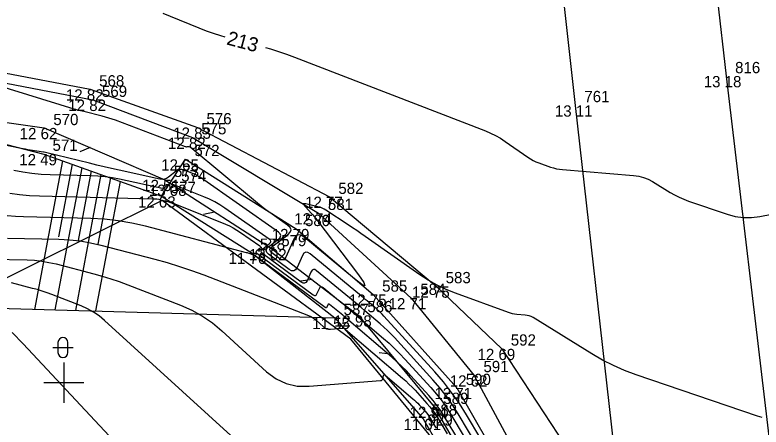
# Model space of a CAD drawing. Extents: x -711234 to -710007, y -1026313 to -1025448.
# Drawn here: x -710926.22 to -710907.65, y -1025876.1 to -1025865.86 of the extents above; entities that cross this region are included whole.
import ezdxf

# ---------------------------------------------------------------- set-up
doc = ezdxf.new("R2010")
doc.units = 0
for name, color, linetype in [('Ex_Contour Labels', 7, 'Continuous'), ('Ex_Major Contours', 7, 'Continuous'), ('Ex_Minor Contours', 7, 'Continuous'), ('Z_betonova_konstrukce', 7, 'Continuous'), ('Z_body', 7, 'Continuous'), ('Z_body_cisla', 7, 'Continuous'), ('Z_body_vysky_redukovane', 7, 'Continuous'), ('Z_hektometricka_sit', 7, 'Continuous'), ('Z_hrany_paty', 7, 'Continuous'), ('Z_katastr_hranice', 7, 'Continuous'), ('Z_katastr_znacky_kultur', 7, 'Continuous'), ('Z_komunikace', 7, 'Continuous'), ('Z_svodidla', 7, 'Continuous'), ('Z_svodidla_znacky', 7, 'Continuous'), ('Z_technicke_srafy', 7, 'Continuous'), ('Z_vdz12_prerusovana', 7, 'Continuous'), ('Z_vdz25_plna', 7, 'Continuous'), ('Z_vdz25_prerusovana', 7, 'Continuous')]:
    doc.layers.add(name, color=color, linetype=linetype)

# ---------------------------------------------------------------- blocks, each defined once
blk = doc.blocks.new('POINT_DISPLAY')
blk.add_line((0, 0), (0, 0))
blk = doc.blocks.new('Z529')
blk.add_line((0, 0), (0.2, 0.2))

msp = doc.modelspace()

# ---------------------------------------------------------------- linework, layer by layer
at = {"layer": 'Ex_Major Contours'}
for points in [[(-710922.532, -1025865.817), (-710922.354, -1025865.89), (-710921.642, -1025866.183), (-710921.462, -1025866.253), (-710921.281, -1025866.317), (-710921.098, -1025866.375), (-710920.995, -1025866.404)], [(-710919.98, -1025866.673), (-710919.86, -1025866.707), (-710919.659, -1025866.769), (-710919.459, -1025866.836), (-710919.262, -1025866.909), (-710914.512, -1025868.743), (-710914.383, -1025868.798), (-710914.258, -1025868.859), (-710914.137, -1025868.928), (-710914.019, -1025869.005), (-710913.453, -1025869.397), (-710913.389, -1025869.439), (-710913.323, -1025869.476), (-710913.254, -1025869.509), (-710913.183, -1025869.537), (-710912.894, -1025869.642), (-710912.821, -1025869.666), (-710912.747, -1025869.685), (-710912.672, -1025869.698), (-710912.596, -1025869.707), (-710910.824, -1025869.85), (-710910.699, -1025869.867), (-710910.579, -1025869.899), (-710910.464, -1025869.945), (-710910.353, -1025870.004), (-710909.918, -1025870.272), (-710909.808, -1025870.335), (-710909.695, -1025870.392), (-710909.579, -1025870.443), (-710909.46, -1025870.488), (-710908.499, -1025870.815), (-710908.297, -1025870.87), (-710908.094, -1025870.898), (-710907.889, -1025870.898), (-710907.682, -1025870.871), (-710905.856, -1025870.512)], [(-710926.346, -1025870.293), (-710926.098, -1025870.326), (-710925.85, -1025870.349), (-710925.6, -1025870.361), (-710922.778, -1025870.429), (-710922.731, -1025870.431), (-710922.685, -1025870.436), (-710922.639, -1025870.444), (-710922.594, -1025870.455), (-710922.413, -1025870.502), (-710922.368, -1025870.514), (-710922.323, -1025870.528), (-710922.279, -1025870.544), (-710922.235, -1025870.56), (-710920.978, -1025871.065), (-710920.88, -1025871.107), (-710920.785, -1025871.155), (-710920.693, -1025871.208), (-710920.604, -1025871.266), (-710920.12, -1025871.604), (-710920.105, -1025871.618), (-710920.099, -1025871.633), (-710920.104, -1025871.648), (-710920.119, -1025871.663), (-710920.199, -1025871.723), (-710920.214, -1025871.738), (-710920.219, -1025871.753), (-710920.214, -1025871.768), (-710920.199, -1025871.783), (-710918.796, -1025872.821), (-710918.767, -1025872.837), (-710918.742, -1025872.838), (-710918.721, -1025872.825), (-710918.703, -1025872.797), (-710918.64, -1025872.658), (-710918.622, -1025872.63), (-710918.602, -1025872.618), (-710918.577, -1025872.62), (-710918.549, -1025872.637), (-710918.077, -1025873.026), (-710917.989, -1025873.1), (-710917.901, -1025873.173), (-710917.813, -1025873.247), (-710917.725, -1025873.322), (-710917.049, -1025873.9), (-710916.909, -1025874.023), (-710916.774, -1025874.15), (-710916.642, -1025874.282), (-710916.514, -1025874.418), (-710915.869, -1025875.124), (-710915.725, -1025875.291), (-710915.589, -1025875.465), (-710915.462, -1025875.645), (-710915.344, -1025875.833), (-710914.755, -1025876.824)], [(-710920.757, -1025876.401), (-710923.985, -1025873.453), (-710924.117, -1025873.343), (-710924.257, -1025873.247), (-710924.406, -1025873.164), (-710924.564, -1025873.094), (-710925.301, -1025872.81), (-710925.417, -1025872.767), (-710925.536, -1025872.727), (-710925.655, -1025872.69), (-710925.775, -1025872.657), (-710926.299, -1025872.52)]]:
    msp.add_lwpolyline(points, dxfattribs=at)
msp.add_lwpolyline([(-710919.793, -1025871.7), (-710919.79, -1025871.7), (-710919.787, -1025871.698), (-710919.785, -1025871.695), (-710919.766, -1025871.653), (-710919.764, -1025871.647), (-710919.764, -1025871.643), (-710919.767, -1025871.644), (-710919.773, -1025871.648), (-710919.811, -1025871.676), (-710919.814, -1025871.679), (-710919.815, -1025871.681), (-710919.814, -1025871.684), (-710919.811, -1025871.687), (-710919.796, -1025871.698)], close=True, dxfattribs=at)
at = {"layer": 'Ex_Minor Contours'}
for points in [[(-710907.626, -1025875.866), (-710907.741, -1025875.835), (-710910.765, -1025874.804), (-710911.049, -1025874.698), (-710911.327, -1025874.576), (-710911.597, -1025874.44), (-710911.86, -1025874.288), (-710913.327, -1025873.385), (-710913.373, -1025873.36), (-710913.421, -1025873.342), (-710913.47, -1025873.328), (-710913.522, -1025873.321), (-710913.733, -1025873.304), (-710913.785, -1025873.298), (-710913.837, -1025873.289), (-710913.888, -1025873.276), (-710913.938, -1025873.26), (-710915.257, -1025872.781), (-710915.49, -1025872.688), (-710915.715, -1025872.581), (-710915.932, -1025872.458), (-710916.142, -1025872.321), (-710917.503, -1025871.367), (-710917.608, -1025871.294), (-710917.714, -1025871.221), (-710917.821, -1025871.15), (-710917.927, -1025871.078), (-710918.479, -1025870.713), (-710918.525, -1025870.686), (-710918.574, -1025870.662), (-710918.624, -1025870.643), (-710918.676, -1025870.628), (-710918.98, -1025870.557), (-710918.987, -1025870.555), (-710918.995, -1025870.554), (-710919.002, -1025870.554), (-710919.009, -1025870.554), (-710919.038, -1025870.555), (-710919.044, -1025870.555), (-710919.046, -1025870.558), (-710919.046, -1025870.561), (-710919.043, -1025870.566), (-710918.842, -1025870.79), (-710918.807, -1025870.829), (-710918.774, -1025870.869), (-710918.741, -1025870.91), (-710918.709, -1025870.952), (-710917.668, -1025872.325), (-710917.536, -1025872.513), (-710917.509, -1025872.592), (-710917.587, -1025872.562), (-710917.77, -1025872.422), (-710919.032, -1025871.381), (-710919.106, -1025871.336), (-710919.171, -1025871.33), (-710919.226, -1025871.364), (-710919.273, -1025871.437), (-710919.474, -1025871.881), (-710919.503, -1025871.926), (-710919.537, -1025871.947), (-710919.578, -1025871.946), (-710919.625, -1025871.92), (-710919.824, -1025871.773), (-710919.861, -1025871.736), (-710919.874, -1025871.699), (-710919.862, -1025871.662), (-710919.825, -1025871.625), (-710919.429, -1025871.327), (-710919.367, -1025871.265), (-710919.347, -1025871.204), (-710919.369, -1025871.144), (-710919.433, -1025871.085), (-710919.82, -1025870.815), (-710919.912, -1025870.749), (-710920.003, -1025870.682), (-710920.092, -1025870.612), (-710920.179, -1025870.541), (-710921.853, -1025869.146), (-710921.862, -1025869.14), (-710921.871, -1025869.137), (-710921.881, -1025869.135), (-710921.891, -1025869.136), (-710921.934, -1025869.143), (-710921.945, -1025869.145), (-710921.956, -1025869.144), (-710921.966, -1025869.143), (-710921.976, -1025869.139), (-710923.716, -1025868.48), (-710923.796, -1025868.451), (-710923.877, -1025868.424), (-710923.959, -1025868.4), (-710924.042, -1025868.379), (-710924.498, -1025868.266), (-710924.539, -1025868.256), (-710924.58, -1025868.246), (-710924.662, -1025868.225), (-710924.683, -1025868.22), (-710924.703, -1025868.214), (-710924.724, -1025868.209), (-710924.744, -1025868.203), (-710927.51, -1025867.351)], [(-710913.915, -1025877.594), (-710914.983, -1025875.798), (-710915.16, -1025875.517), (-710915.351, -1025875.245), (-710915.555, -1025874.984), (-710915.773, -1025874.732), (-710917.038, -1025873.346), (-710917.081, -1025873.301), (-710917.125, -1025873.257), (-710917.17, -1025873.214), (-710917.216, -1025873.173), (-710917.405, -1025873.012), (-710917.453, -1025872.971), (-710917.5, -1025872.931), (-710917.548, -1025872.891), (-710917.596, -1025872.852), (-710918.871, -1025871.8), (-710918.93, -1025871.764), (-710918.981, -1025871.759), (-710919.025, -1025871.786), (-710919.062, -1025871.844), (-710919.195, -1025872.138), (-710919.232, -1025872.196), (-710919.277, -1025872.224), (-710919.331, -1025872.222), (-710919.391, -1025872.189), (-710919.905, -1025871.809), (-710919.951, -1025871.763), (-710919.967, -1025871.717), (-710919.952, -1025871.671), (-710919.905, -1025871.624), (-710919.659, -1025871.439), (-710919.613, -1025871.393), (-710919.598, -1025871.347), (-710919.614, -1025871.302), (-710919.662, -1025871.258), (-710921.602, -1025869.906), (-710921.65, -1025869.875), (-710921.698, -1025869.847), (-710921.749, -1025869.821), (-710921.8, -1025869.799), (-710922.01, -1025869.715), (-710922.062, -1025869.701), (-710922.111, -1025869.701), (-710922.159, -1025869.715), (-710922.204, -1025869.742), (-710922.398, -1025869.895), (-710922.446, -1025869.925), (-710922.497, -1025869.944), (-710922.552, -1025869.95), (-710922.609, -1025869.943), (-710923.626, -1025869.721), (-710923.81, -1025869.68), (-710923.994, -1025869.638), (-710924.178, -1025869.594), (-710924.362, -1025869.55), (-710925.454, -1025869.281), (-710925.49, -1025869.272), (-710925.499, -1025869.27), (-710925.508, -1025869.269), (-710925.839, -1025869.22), (-710925.895, -1025869.211), (-710925.951, -1025869.202), (-710926.008, -1025869.191), (-710926.064, -1025869.18), (-710927.956, -1025868.79)], [(-710914.335, -1025877.209), (-710915.164, -1025875.815), (-710915.311, -1025875.581), (-710915.47, -1025875.355), (-710915.64, -1025875.137), (-710915.821, -1025874.928), (-710916.776, -1025873.882), (-710916.861, -1025873.791), (-710916.949, -1025873.703), (-710917.04, -1025873.619), (-710917.133, -1025873.536), (-710917.511, -1025873.213), (-710917.606, -1025873.133), (-710917.701, -1025873.052), (-710917.796, -1025872.973), (-710917.892, -1025872.893), (-710918.71, -1025872.218), (-710918.753, -1025872.192), (-710918.791, -1025872.188), (-710918.824, -1025872.208), (-710918.851, -1025872.251), (-710918.949, -1025872.467), (-710918.976, -1025872.51), (-710919.01, -1025872.531), (-710919.049, -1025872.529), (-710919.094, -1025872.505), (-710920.052, -1025871.796), (-710920.083, -1025871.765), (-710920.093, -1025871.735), (-710920.083, -1025871.704), (-710920.052, -1025871.674), (-710919.889, -1025871.551), (-710919.858, -1025871.52), (-710919.849, -1025871.49), (-710919.859, -1025871.46), (-710919.891, -1025871.431), (-710920.99, -1025870.665), (-710921.116, -1025870.583), (-710921.246, -1025870.508), (-710921.379, -1025870.44), (-710921.517, -1025870.38), (-710922.305, -1025870.064), (-710922.331, -1025870.057), (-710922.355, -1025870.057), (-710922.379, -1025870.064), (-710922.401, -1025870.078), (-710922.489, -1025870.147), (-710922.512, -1025870.162), (-710922.536, -1025870.17), (-710922.561, -1025870.173), (-710922.588, -1025870.17), (-710923.612, -1025869.946), (-710923.792, -1025869.911), (-710923.973, -1025869.885), (-710924.156, -1025869.868), (-710924.339, -1025869.859), (-710925.339, -1025869.835), (-710925.566, -1025869.824), (-710925.792, -1025869.804), (-710926.017, -1025869.773), (-710926.241, -1025869.732)], [(-710915.158, -1025876.467), (-710915.525, -1025875.85), (-710915.613, -1025875.71), (-710915.708, -1025875.575), (-710915.809, -1025875.445), (-710915.918, -1025875.32), (-710916.364, -1025874.831), (-710916.478, -1025874.71), (-710916.595, -1025874.593), (-710916.715, -1025874.48), (-710916.839, -1025874.371), (-710918.022, -1025873.36), (-710918.061, -1025873.327), (-710918.1, -1025873.294), (-710918.139, -1025873.261), (-710918.179, -1025873.228), (-710918.389, -1025873.055), (-710918.401, -1025873.048), (-710918.412, -1025873.047), (-710918.421, -1025873.052), (-710918.429, -1025873.064), (-710918.457, -1025873.126), (-710918.465, -1025873.139), (-710918.474, -1025873.145), (-710918.485, -1025873.144), (-710918.498, -1025873.137), (-710920.205, -1025871.874), (-710920.223, -1025871.861), (-710920.242, -1025871.85), (-710920.262, -1025871.84), (-710920.283, -1025871.831), (-710920.366, -1025871.799), (-710920.388, -1025871.791), (-710920.409, -1025871.784), (-710920.43, -1025871.777), (-710920.452, -1025871.771), (-710922.968, -1025871.115), (-710923.304, -1025871.038), (-710923.644, -1025870.98), (-710923.986, -1025870.942), (-710924.331, -1025870.924), (-710926.001, -1025870.883), (-710926.204, -1025870.874), (-710926.406, -1025870.856)], [(-710926.403, -1025871.406), (-710925.122, -1025871.437), (-710924.858, -1025871.451), (-710924.596, -1025871.48), (-710924.336, -1025871.524), (-710924.078, -1025871.584), (-710922.735, -1025871.934), (-710922.427, -1025872.019), (-710922.122, -1025872.112), (-710921.82, -1025872.215), (-710921.52, -1025872.325), (-710918.91, -1025873.333), (-710918.858, -1025873.356), (-710918.809, -1025873.383), (-710918.763, -1025873.415), (-710918.72, -1025873.451), (-710918.542, -1025873.613), (-710918.503, -1025873.643), (-710918.461, -1025873.663), (-710918.415, -1025873.673), (-710918.366, -1025873.674), (-710918.07, -1025873.65), (-710918.067, -1025873.649), (-710918.064, -1025873.648), (-710918.062, -1025873.646), (-710918.061, -1025873.643), (-710918.058, -1025873.629), (-710918.057, -1025873.626), (-710918.055, -1025873.625), (-710918.053, -1025873.625), (-710918.051, -1025873.627), (-710916.576, -1025874.887), (-710916.494, -1025874.96), (-710916.414, -1025875.035), (-710916.336, -1025875.112), (-710916.261, -1025875.192), (-710915.966, -1025875.516), (-710915.894, -1025875.599), (-710915.827, -1025875.685), (-710915.764, -1025875.774), (-710915.706, -1025875.867), (-710915.463, -1025876.275)], [(-710926.804, -1025871.929), (-710925.914, -1025871.95), (-710925.731, -1025871.96), (-710925.549, -1025871.98), (-710925.368, -1025872.011), (-710925.189, -1025872.052), (-710924.255, -1025872.295), (-710924.041, -1025872.354), (-710923.829, -1025872.419), (-710923.619, -1025872.491), (-710923.41, -1025872.568), (-710922.098, -1025873.075), (-710921.817, -1025873.198), (-710921.552, -1025873.345), (-710921.302, -1025873.517), (-710921.066, -1025873.713), (-710919.954, -1025874.729), (-710919.719, -1025874.906), (-710919.465, -1025875.025), (-710919.191, -1025875.087), (-710918.898, -1025875.092), (-710917.119, -1025874.95), (-710917.1, -1025874.946), (-710917.085, -1025874.937), (-710917.074, -1025874.924), (-710917.067, -1025874.906), (-710917.048, -1025874.825), (-710917.041, -1025874.809), (-710917.032, -1025874.801), (-710917.021, -1025874.802), (-710917.006, -1025874.812), (-710916.313, -1025875.404), (-710916.272, -1025875.439), (-710916.233, -1025875.476), (-710916.195, -1025875.514), (-710916.159, -1025875.553), (-710916.014, -1025875.712), (-710915.979, -1025875.752), (-710915.946, -1025875.795), (-710915.915, -1025875.838), (-710915.887, -1025875.884), (-710915.768, -1025876.084), (-710915.739, -1025876.133)], [(-710926.286, -1025873.758), (-710926.192, -1025873.849), (-710926.1, -1025873.942), (-710926.01, -1025874.036), (-710922.921, -1025877.343)]]:
    msp.add_lwpolyline(points, dxfattribs=at)
at = {"layer": 'Z_betonova_konstrukce'}
for p, q in [((-710922.57, -1025870.37), (-710921.97, -1025869.45)), ((-710921.97, -1025869.45), (-710919.22, -1025871.18)), ((-710922.57, -1025870.37), (-710920.34, -1025871.77)), ((-710919.22, -1025871.18), (-710917.3, -1025872.81)), ((-710920.34, -1025871.77), (-710918.26, -1025873.39)), ((-710917.3, -1025872.81), (-710915.22, -1025875.13)), ((-710918.26, -1025873.39), (-710916.06, -1025875.9)), ((-710915.22, -1025875.13), (-710913.68, -1025877.81)), ((-710916.06, -1025875.9), (-710914.66, -1025878.32))]:
    msp.add_line(p, q, dxfattribs=at)
at = {"layer": 'Z_hektometricka_sit'}
for p, q in [((-710925, -1025874.5), (-710925, -1025875.5)), ((-710925.5, -1025875), (-710924.5, -1025875))]:
    msp.add_line(p, q, dxfattribs=at)
at = {"layer": 'Z_hrany_paty'}
for p, q in [((-710928.21, -1025868.62), (-710925.5, -1025869.32)), ((-710925.5, -1025869.32), (-710922.57, -1025870.37)), ((-710927.72, -1025873.12), (-710918.26, -1025873.39))]:
    msp.add_line(p, q, dxfattribs=at)
at = {"layer": 'Z_katastr_hranice'}
msp.add_lwpolyline([(-710916.27, -1025887.83), (-710912.66, -1025887.06), (-710913.91, -1025880.81), (-710915.91, -1025876.29), (-710917.86, -1025873.92), (-710922.55, -1025870.47), (-710934.23, -1025876.27)], dxfattribs=at)
at = {"layer": 'Z_katastr_znacky_kultur'}
for p, q in [((-710925.27, -1025874.13), (-710924.77, -1025874.13)), ((-710925.145, -1025874.005), (-710925.145, -1025874.256)), ((-710924.895, -1025874.256), (-710924.895, -1025874.005))]:
    msp.add_line(p, q, dxfattribs=at)
for centre, start, end in [((-710925.02, -1025874.005), 0, 180), ((-710925.02, -1025874.255), 180, 359.9879)]:
    msp.add_arc(centre, 0.125, start, end, dxfattribs=at)
at = {"layer": 'Z_komunikace'}
for p, q in [((-710927.98, -1025867.26), (-710924.28, -1025867.97)), ((-710924.28, -1025867.97), (-710921.8, -1025868.91)), ((-710921.8, -1025868.91), (-710918.66, -1025870.79)), ((-710918.66, -1025870.79), (-710916.36, -1025872.9)), ((-710916.36, -1025872.9), (-710914.79, -1025874.82)), ((-710914.79, -1025874.82), (-710913.31, -1025877.56))]:
    msp.add_line(p, q, dxfattribs=at)
at = {"layer": 'Z_svodidla'}
for p, q in [((-710928.12, -1025868.29), (-710925.49, -1025868.67)), ((-710925.49, -1025868.67), (-710922.49, -1025869.96)), ((-710922.49, -1025869.96), (-710922.3, -1025870.08)), ((-710922.3, -1025870.08), (-710919.81, -1025871.68)), ((-710919.81, -1025871.68), (-710917.67, -1025873.33)), ((-710917.67, -1025873.33), (-710915.79, -1025875.6)), ((-710915.79, -1025875.6), (-710914.34, -1025878.08))]:
    msp.add_line(p, q, dxfattribs=at)
at = {"layer": 'Z_technicke_srafy'}
for p, q in [((-710925.03, -1025869.49), (-710925.73, -1025873.18)), ((-710924.55, -1025869.66), (-710925.22, -1025873.19)), ((-710924.79, -1025869.57), (-710925.13, -1025871.38)), ((-710924.08, -1025869.83), (-710924.71, -1025873.21)), ((-710924.32, -1025869.74), (-710924.64, -1025871.47)), ((-710923.6, -1025870), (-710924.21, -1025873.22)), ((-710923.84, -1025869.91), (-710924.15, -1025871.56))]:
    msp.add_line(p, q, dxfattribs=at)
at = {"layer": 'Z_vdz12_prerusovana'}
for p, q in [((-710910.35, -1025851.77), (-710908.52, -1025867.38)), ((-710908.52, -1025867.38), (-710907.16, -1025878.89))]:
    msp.add_line(p, q, dxfattribs=at)
at = {"layer": 'Z_vdz25_plna'}
for p, q in [((-710927.94, -1025867.02), (-710924.34, -1025867.71)), ((-710924.34, -1025867.71), (-710921.67, -1025868.66)), ((-710921.67, -1025868.66), (-710918.39, -1025870.38)), ((-710918.39, -1025870.38), (-710915.73, -1025872.61)), ((-710915.73, -1025872.61), (-710914.1, -1025874.16)), ((-710914.1, -1025874.16), (-710912.26, -1025876.96))]:
    msp.add_line(p, q, dxfattribs=at)
at = {"layer": 'Z_vdz25_prerusovana'}
for p, q in [((-710912.27, -1025868.11), (-710913.49, -1025857.09)), ((-710910.95, -1025879.77), (-710912.27, -1025868.11))]:
    msp.add_line(p, q, dxfattribs=at)

# ---------------------------------------------------------------- block references
at = {"layer": 'Z_body'}
for p in [(-710908.52, -1025867.38), (-710924.34, -1025867.71), (-710924.28, -1025867.97), (-710912.27, -1025868.11), (-710925.49, -1025868.67), (-710921.67, -1025868.66), (-710921.8, -1025868.91), (-710925.5, -1025869.32), (-710921.97, -1025869.45), (-710922.49, -1025869.96), (-710922.3, -1025870.08), (-710922.57, -1025870.37), (-710918.39, -1025870.38), (-710918.66, -1025870.79), (-710919.22, -1025871.18), (-710919.81, -1025871.68), (-710920.34, -1025871.77), (-710915.73, -1025872.61), (-710917.3, -1025872.81), (-710916.36, -1025872.9), (-710918.26, -1025873.39), (-710917.67, -1025873.33), (-710914.1, -1025874.16), (-710914.79, -1025874.82), (-710915.22, -1025875.13), (-710915.79, -1025875.6), (-710916.06, -1025875.9)]:
    msp.add_blockref('POINT_DISPLAY', p, dxfattribs=at)
at = {"layer": 'Z_svodidla_znacky'}
for p, rotation in [((-710924.34, -1025869.16), 156.7), ((-710921.25, -1025870.76), 147.3), ((-710918.82, -1025872.44), 142.4), ((-710916.87, -1025874.29), 129.6)]:
    msp.add_blockref('Z529', p, dxfattribs=dict(at, rotation=rotation))

# ---------------------------------------------------------------- texts
at = {"layer": 'Ex_Contour Labels'}
msp.add_text('213', height=0.35, rotation=345.1381, dxfattribs=at).set_placement((-710920.969, -1025866.592))
at = {"layer": 'Z_body_cisla'}
for s, p in [('816', (-710908.3, -1025867.31)), ('568', (-710924.12, -1025867.64)), ('569', (-710924.05, -1025867.9)), ('761', (-710912.05, -1025868.03)), ('570', (-710925.26, -1025868.6)), ('576', (-710921.45, -1025868.58)), ('575', (-710921.58, -1025868.83)), ('571', (-710925.28, -1025869.24)), ('572', (-710921.75, -1025869.37)), ('573', (-710922.26, -1025869.89)), ('574', (-710922.08, -1025870)), ('577', (-710922.34, -1025870.29)), ('582', (-710918.17, -1025870.31)), ('581', (-710918.43, -1025870.71)), ('580', (-710919, -1025871.11)), ('579', (-710919.59, -1025871.61)), ('578', (-710920.12, -1025871.7)), ('583', (-710915.5, -1025872.53)), ('585', (-710917.08, -1025872.74)), ('584', (-710916.13, -1025872.82)), ('586', (-710917.45, -1025873.25)), ('587', (-710918.04, -1025873.32)), ('592', (-710913.88, -1025874.08)), ('591', (-710914.56, -1025874.74)), ('590', (-710915, -1025875.06)), ('589', (-710915.56, -1025875.53)), ('588', (-710915.84, -1025875.82)), ('929', (-710915.95, -1025876.07))]:
    msp.add_text(s, height=0.28, dxfattribs=at).set_placement(p)
at = {"layer": 'Z_body_vysky_redukovane'}
for s, p in [('13 18', (-710909.08, -1025867.66)), ('12 82', (-710924.947, -1025867.99)), ('12 82', (-710924.887, -1025868.25)), ('13 11', (-710912.783, -1025868.39)), ('12 62', (-710926.097, -1025868.95)), ('12 83', (-710922.277, -1025868.94)), ('12 82', (-710922.407, -1025869.19)), ('12 49', (-710926.107, -1025869.6)), ('12 65', (-710922.577, -1025869.73)), ('12 51', (-710923.05, -1025870.24)), ('13 08', (-710922.883, -1025870.36)), ('12 03', (-710923.153, -1025870.65)), ('12 77', (-710918.997, -1025870.66)), ('12 74', (-710919.267, -1025871.07)), ('12 79', (-710919.827, -1025871.46)), ('13 02', (-710920.393, -1025871.96)), ('11 76', (-710920.9, -1025872.05)), ('12 75', (-710916.337, -1025872.89)), ('12 75', (-710917.907, -1025873.09)), ('12 71', (-710916.92, -1025873.18)), ('11 55', (-710918.82, -1025873.67)), ('12 98', (-710918.277, -1025873.61)), ('12 69', (-710914.707, -1025874.44)), ('12 62', (-710915.397, -1025875.1)), ('12 71', (-710915.78, -1025875.41)), ('12 94', (-710916.397, -1025875.88)), ('11 01', (-710916.55, -1025876.18))]:
    msp.add_text(s, height=0.28, dxfattribs=at).set_placement(p)

doc.saveas('drawing.dxf')
